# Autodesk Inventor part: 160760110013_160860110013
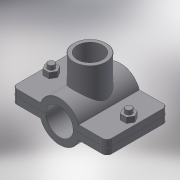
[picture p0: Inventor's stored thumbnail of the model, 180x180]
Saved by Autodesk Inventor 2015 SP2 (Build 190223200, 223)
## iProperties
Created: 2017-05
Part Number: 160760110013_160860110013
Material: Generic
Description: PLASSON SADDLE 110-1.1/4"
Document SubType Name: Modeling
Designer: KIM
Density: 1 g/cm^3
Appearance: Default
Author: KIM
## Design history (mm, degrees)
derived "16076.ipt"
feature "Solid1::16076.ipt"
feature "Solid2::16076.ipt"
tag "TaggingFeature1"
body "Solid1"
other parameters: "d0" = 121, "d1" = 165, "d2" = 55, "d4" = 116, "d5" = 0, "d6" = 8.25, "d7" = 165, "d8" = 0.1, "d10" = 0, "d11" = 1.1, "d14" = 50.6376, "d20" = 1.1, "d23" = 1.1, "d36" = 13, "d37" = 10.4, "d38" = 63, "d39" = 0, "d40" = 3, "d41" = 5, "d42" = 0, "d43" = 8, "d44" = 3, "d45" = 0, "d46" = 1.1, "d51" = 91, "d52" = 38.952, "d53" = 25, "d54" = 0, "d55" = 32, "d57" = 0, "d58" = 118.8, "d60" = 0, "d62" = 13, "d63" = 10.4, "d66" = 95.2, "B_" = 32, "G_" = 38.952, "A_" = 91, "L_" = 165, "L_1" = 116, "l_2" = 25
